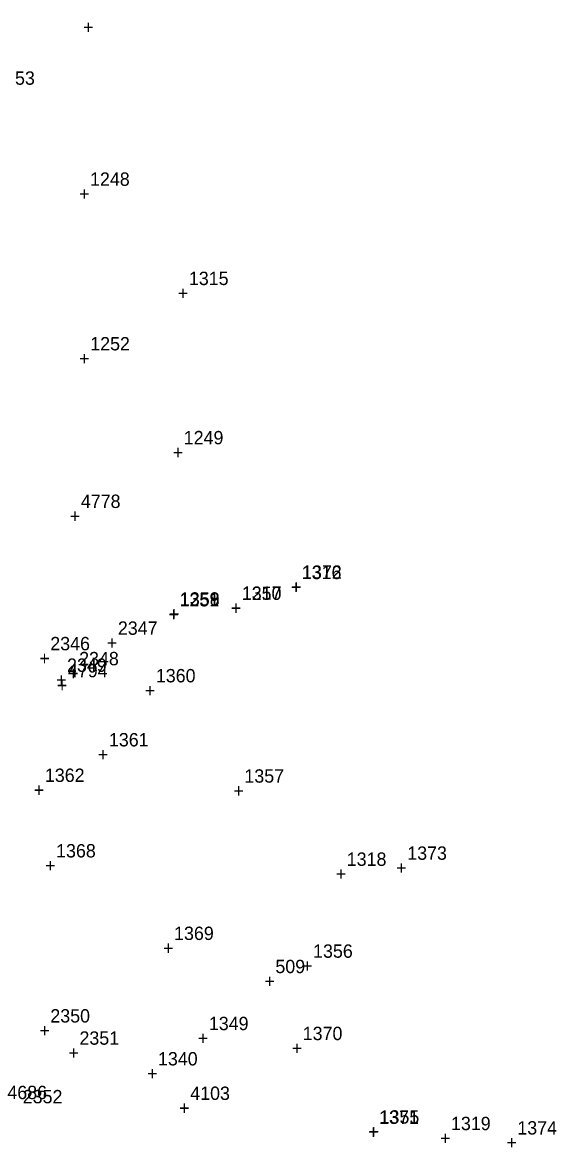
# Model space of a CAD drawing. Extents: x 1036751 to 1042192, y 772604 to 785439.
# Drawn here: x 1037845.1 to 1037945.3, y 780538.7 to 780749.5 of the extents above; entities that cross this region are included whole.
import ezdxf

# ---------------------------------------------------------------- set-up
doc = ezdxf.new("R2010")
doc.units = 0
for name, color, linetype in [('S_Control_Traverse_Point', 7, 'Continuous'), ('S_Ground_Elevation', 7, 'Continuous'), ('S_Ground_LevelString', 7, 'Continuous'), ('S_Roadway_Centerline', 7, 'Continuous'), ('S_Roadway_Edge_Pavement', 7, 'Continuous'), ('S_Traffic_Sign_SinglePost', 7, 'Continuous'), ('S_Utilities_GuyWire3', 7, 'Continuous'), ('S_Utilities_Pole_Brace3', 7, 'Continuous'), ('S_Utilities_Pole_Power', 7, 'Continuous'), ('S_Utilities_UG_Water_Line', 7, 'Continuous')]:
    doc.layers.add(name, color=color, linetype=linetype)

msp = doc.modelspace()

# ---------------------------------------------------------------- texts
at = {"layer": 'S_Control_Traverse_Point'}
for s, p in [('509', (1037892.56, 780571.38)), ('509', (1037892.56, 780571.38)), ('509', (1037892.56, 780571.38)), ('509', (1037892.56, 780571.38)), ('509', (1037892.56, 780571.38)), ('509', (1037892.56, 780571.38)), ('509', (1037892.56, 780571.38)), ('509', (1037892.56, 780571.38)), ('509', (1037892.56, 780571.38)), ('509', (1037892.56, 780571.38)), ('509', (1037892.56, 780571.38)), ('+', (1037890.5, 780568.63)), ('+', (1037890.5, 780568.63)), ('+', (1037890.5, 780568.63)), ('+', (1037890.5, 780568.63)), ('+', (1037890.5, 780568.63)), ('+', (1037890.5, 780568.63)), ('+', (1037890.5, 780568.63)), ('+', (1037890.5, 780568.63)), ('+', (1037890.5, 780568.63)), ('+', (1037890.5, 780568.63)), ('+', (1037890.5, 780568.63))]:
    msp.add_text(s, height=2.5, dxfattribs=at).set_placement(p)
at = {"layer": 'S_Ground_Elevation'}
for s, p in [('4778', (1037856.09, 780658.51)), ('+', (1037854.02, 780655.76)), ('4794', (1037853.67, 780626.8)), ('+', (1037851.61, 780624.05)), ('4686', (1037842.31, 780547.78))]:
    msp.add_text(s, height=2.5, dxfattribs=at).set_placement(p)
at = {"layer": 'S_Ground_LevelString'}
for s, p in [('1358', (1037874.67, 780640.2)), ('+', (1037872.61, 780637.45)), ('1357', (1037886.75, 780607.06)), ('+', (1037884.68, 780604.31)), ('1368', (1037851.45, 780593.05)), ('+', (1037849.39, 780590.3)), ('1369', (1037873.57, 780577.59)), ('+', (1037871.51, 780574.84)), ('1356', (1037899.63, 780574.26)), ('+', (1037897.57, 780571.51)), ('1370', (1037897.69, 780558.83)), ('+', (1037895.63, 780556.08)), ('1371', (1037912, 780543.14)), ('1355', (1037912.1, 780543.2)), ('+', (1037909.94, 780540.39)), ('+', (1037910.04, 780540.45))]:
    msp.add_text(s, height=2.5, dxfattribs=at).set_placement(p)
at = {"layer": 'S_Roadway_Centerline'}
for s, p in [('1248', (1037857.81, 780718.86)), ('+', (1037855.75, 780716.11)), ('1249', (1037875.38, 780670.44)), ('+', (1037873.32, 780667.69)), ('1250', (1037886.26, 780641.28)), ('1317', (1037886.27, 780641.31)), ('+', (1037884.19, 780638.53)), ('+', (1037884.21, 780638.56)), ('1318', (1037905.94, 780591.48)), ('+', (1037903.88, 780588.73)), ('1349', (1037880.09, 780560.7)), ('+', (1037878.03, 780557.95)), ('1319', (1037925.48, 780541.97)), ('+', (1037923.42, 780539.22))]:
    msp.add_text(s, height=2.5, dxfattribs=at).set_placement(p)
at = {"layer": 'S_Roadway_Edge_Pavement'}
for s, p in [('+', (1037856.54, 780747.35)), ('1253', (1037840.03, 780737.79)), ('1315', (1037876.35, 780700.27)), ('+', (1037874.29, 780697.52)), ('1252', (1037857.85, 780688.03)), ('+', (1037855.79, 780685.28)), ('1316', (1037897.5, 780645.19)), ('1372', (1037897.57, 780645.26)), ('+', (1037895.44, 780642.44)), ('+', (1037895.51, 780642.51)), ('1251', (1037874.58, 780640.07)), ('1359', (1037874.64, 780640.22)), ('+', (1037872.52, 780637.32)), ('+', (1037872.58, 780637.47)), ('1360', (1037870.15, 780625.85)), ('+', (1037868.09, 780623.1)), ('1361', (1037861.35, 780613.85)), ('+', (1037859.29, 780611.1)), ('1362', (1037849.35, 780607.2)), ('+', (1037847.29, 780604.45)), ('1373', (1037917.28, 780592.61)), ('+', (1037915.21, 780589.86)), ('1340', (1037870.55, 780554.09)), ('+', (1037868.49, 780551.34)), ('1374', (1037937.92, 780541.15)), ('+', (1037935.86, 780538.4))]:
    msp.add_text(s, height=2.5, dxfattribs=at).set_placement(p)
at = {"layer": 'S_Traffic_Sign_SinglePost'}
for s, p in [('2346', (1037850.36, 780631.86)), ('+', (1037848.3, 780629.11)), ('2350', (1037850.37, 780562.13)), ('+', (1037848.31, 780559.38))]:
    msp.add_text(s, height=2.5, dxfattribs=at).set_placement(p)
at = {"layer": 'S_Utilities_GuyWire3'}
for s, p in [('2348', (1037855.77, 780629.05)), ('2349', (1037853.5, 780627.82)), ('+', (1037853.71, 780626.3)), ('+', (1037851.44, 780625.07))]:
    msp.add_text(s, height=2.5, dxfattribs=at).set_placement(p)
at = {"layer": 'S_Utilities_Pole_Brace3'}
msp.add_text('2352', height=2.5, dxfattribs=at).set_placement((1037845.2, 780547))
at = {"layer": 'S_Utilities_Pole_Power'}
for s, p in [('2347', (1037863.03, 780634.76)), ('+', (1037860.97, 780632.01)), ('2351', (1037855.83, 780557.97)), ('+', (1037853.77, 780555.22))]:
    msp.add_text(s, height=2.5, dxfattribs=at).set_placement(p)
at = {"layer": 'S_Utilities_UG_Water_Line'}
for s, p in [('4103', (1037876.6, 780547.63)), ('+', (1037874.54, 780544.88))]:
    msp.add_text(s, height=2.5, dxfattribs=at).set_placement(p)

doc.saveas('drawing.dxf')
